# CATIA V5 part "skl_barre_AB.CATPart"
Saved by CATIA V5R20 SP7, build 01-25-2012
Part number: skl_barre_AB
Publications: "Droite.4", "Droite.5", "Droite.6", "Point.A'", "PointA", "Point.B"
Bounding box of the stored display mesh (mm): x 75 to 75, y 30 to 110, z -50 to 0
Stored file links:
  D:\IFMA\COURS\2A\projet balance IAO\catia\skl_barre_AB.CATPart
  D:\IFMA\COURS\2A\projet balance IAO\catia\Skl_projet_balance.CATProduct
  D:\IFMA\COURS\2A\projet balance IAO\catia\skl_general.CATPart
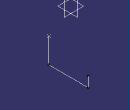
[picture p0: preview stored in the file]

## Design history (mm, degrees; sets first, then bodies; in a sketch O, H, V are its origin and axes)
Set1
  Point1 "Point.A'": linked copy from another document
  Point2 "Point.B": linked copy from another document
  Point3 "Point.A": linked copy from another document
  Plane1 "Plan_AB": linked copy from another document
  Plane2 "Plan.AB'": linked copy from another document
  Plane3 "Plan.KDAF": linked copy from another document
Body1 (main body)
  Line1: type PtPt, FirstPoint Point1, SecondPoint Point3
  Line2: type PtPt, FirstPoint Point1, SecondPoint Point2
  Plane4 "Plan.AB'": stored without definition
  Line3: type PtDir, RefPoint Point2, Direction xy-plane, Start 0, End 20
